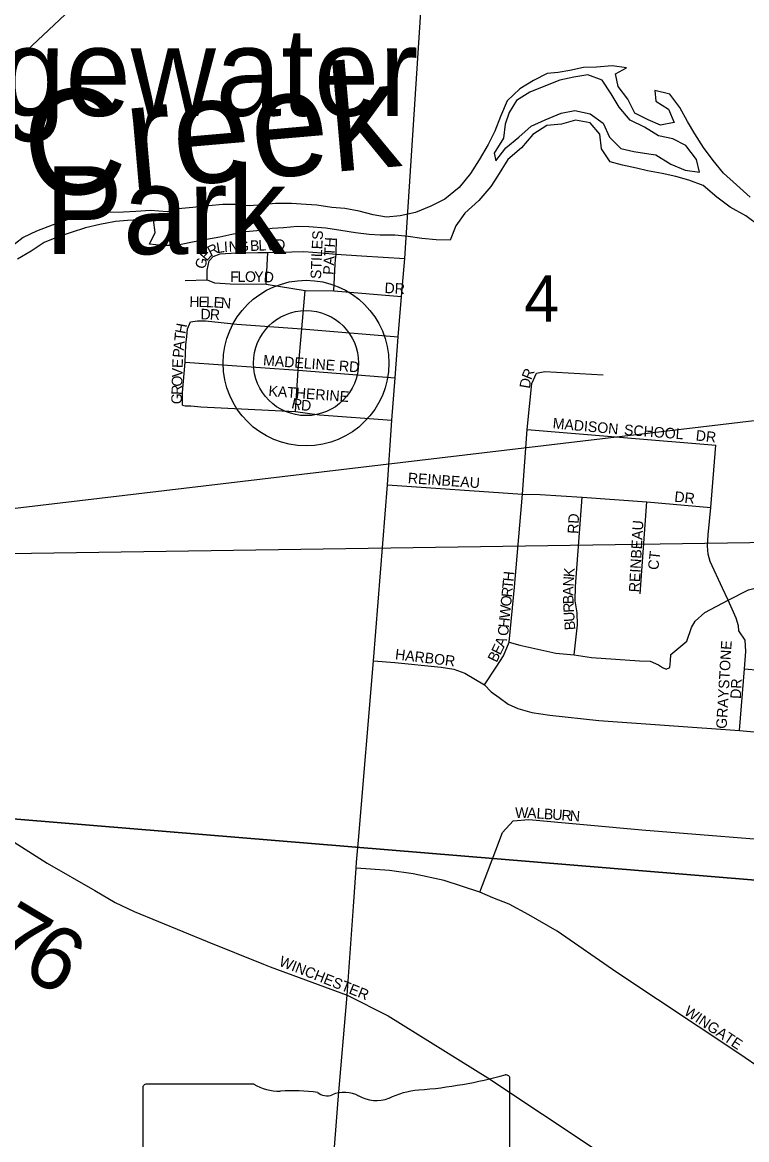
# Model space of a CAD drawing. Extents: x 0 to 34, y 0 to 22.
# Drawn here: x 6.374 to 7.024, y 16.825 to 17.828 of the extents above; entities that cross this region are included whole.
import ezdxf

# ---------------------------------------------------------------- set-up
doc = ezdxf.new("R2010")
doc.units = 0
for name, color, linetype in [('BD_P_Text', 7, 'Continuous'), ('GM_X_City_Street', 7, 'Continuous'), ('GM_X_City_Street_Text', 7, 'Continuous'), ('GM_X_County_Road', 7, 'Continuous'), ('GM_X_County_Road_Text', 7, 'Continuous'), ('GM_X_Interstate_Route', 7, 'Continuous'), ('GM_X_Major_River', 7, 'Continuous'), ('GM_X_Major_River_Text', 7, 'Continuous'), ('GM_X_Section', 7, 'Continuous'), ('GM_X_Section_Text', 7, 'Continuous'), ('GM_X_State_Route', 7, 'Continuous'), ('GM_X_State_Shield', 7, 'Continuous'), ('GM_X_Township_Subdivision', 7, 'Continuous'), ('GM_X_Township_Subdivision_Text', 7, 'Continuous'), ('GM_X_Unincorporated', 7, 'Continuous'), ('GM_X_Unincorporated_Location', 7, 'Continuous'), ('GM_X_Unincorporated_Text', 7, 'Continuous')]:
    doc.layers.add(name, color=color, linetype=linetype)

msp = doc.modelspace()

# ---------------------------------------------------------------- linework, layer by layer
at = {"layer": 'BD_P_Text'}
msp.add_lwpolyline([(9.7485, 17.7931), (5.9787, 17.3454), (9.7485, 17.4014)], close=True, dxfattribs=at)
at = {"layer": 'GM_X_City_Street'}
msp.add_lwpolyline([(6.5904, 16.9823), (6.5965, 16.9798), (6.6655, 16.9545), (6.7025, 16.9357), (6.7917, 16.88), (6.9382, 16.7826), (7.1077, 16.6702), (7.1098, 16.6688)], dxfattribs=at)
at = {"layer": 'GM_X_County_Road'}
msp.add_lwpolyline([(5.1496, 17.8918), (5.1573, 17.8838), (5.1678, 17.876), (5.3625, 17.7509), (5.6653, 17.5523), (5.7694, 17.4837), (5.8147, 17.4543), (5.8758, 17.4145), (5.8966, 17.4004), (5.9787, 17.3454), (5.9879, 17.3394), (6.1472, 17.2345), (6.3013, 17.1331), (6.3963, 17.0731), (6.4389, 17.0483), (6.4571, 17.0376), (6.4744, 17.0295), (6.5397, 17.0026), (6.5904, 16.9823)], dxfattribs=at)
at = {"layer": 'GM_X_Interstate_Route'}
msp.add_lwpolyline([(6.6338, 18.046), (6.5392, 17.957), (6.4517, 17.8729), (6.3828, 17.8077), (6.3064, 17.727), (6.2509, 17.6728), (6.2053, 17.6234), (6.1901, 17.6054)], dxfattribs=at)
at = {"layer": 'GM_X_Major_River'}
for points in [[(7.0273, 17.6715), (7.0152, 17.6825), (7.0034, 17.6931), (6.9943, 17.7045), (6.9856, 17.7159), (6.9777, 17.7284), (6.9712, 17.7394), (6.9644, 17.7519), (6.9553, 17.764), (6.9417, 17.7674), (6.9428, 17.7576), (6.9542, 17.7504), (6.9591, 17.7386), (6.947, 17.736), (6.9357, 17.7409), (6.9239, 17.7469), (6.9175, 17.7595), (6.9088, 17.7708), (6.9065, 17.7822), (6.9164, 17.7875), (6.9035, 17.7894), (6.8895, 17.7883), (6.8777, 17.7879), (6.8656, 17.7852), (6.855, 17.7833), (6.8452, 17.7825), (6.833, 17.7761), (6.8206, 17.7689), (6.8092, 17.7579), (6.8031, 17.7438), (6.7982, 17.7306), (6.7921, 17.7188), (6.7842, 17.7051), (6.7762, 17.6926), (6.766, 17.6801), (6.7531, 17.6695), (6.7406, 17.6634), (6.727, 17.6577), (6.713, 17.6547), (6.7009, 17.6535), (6.6888, 17.6554), (6.6763, 17.6588), (6.6634, 17.6611), (6.6517, 17.6622), (6.6384, 17.6641), (6.6286, 17.6649), (6.6157, 17.6656), (6.6013, 17.6656), (6.5896, 17.6645), (6.5774, 17.6637), (6.5646, 17.6648), (6.554, 17.6648), (6.5411, 17.6637), (6.5271, 17.6621), (6.5138, 17.661), (6.504, 17.6583), (6.4889, 17.6594), (6.4758, 17.6585), (6.4646, 17.6579), (6.4502, 17.6576), (6.4396, 17.656), (6.426, 17.6553), (6.4108, 17.6499), (6.4006, 17.6461), (6.3866, 17.6408), (6.3745, 17.6351), (6.3609, 17.6245)], [(6.9428, 17.7094), (6.9561, 17.7011), (6.969, 17.6958), (6.9818, 17.6939), (6.9792, 17.7053), (6.9697, 17.7178), (6.958, 17.7238), (6.9451, 17.7265), (6.9326, 17.7344), (6.9198, 17.7405), (6.9099, 17.7522), (6.9027, 17.7644), (6.8944, 17.7765), (6.8815, 17.7814), (6.869, 17.7791), (6.8565, 17.7765), (6.8436, 17.7715), (6.8296, 17.7659), (6.8175, 17.7583), (6.8111, 17.7476), (6.8073, 17.737), (6.8058, 17.7245), (6.7974, 17.7108), (6.799, 17.704)], [(7.0364, 17.645), (7.0235, 17.6545), (7.0095, 17.6624), (6.9974, 17.6715), (6.9852, 17.6818), (6.9724, 17.6867), (6.9606, 17.6901), (6.9485, 17.6927), (6.9353, 17.695), (6.9254, 17.6976), (6.9129, 17.7003), (6.9016, 17.7033), (6.894, 17.7147), (6.8925, 17.728), (6.8838, 17.7382), (6.8705, 17.7405), (6.858, 17.737), (6.8448, 17.7359), (6.8323, 17.7276), (6.8221, 17.7158), (6.8099, 17.7052), (6.8005, 17.6904), (6.7944, 17.6809), (6.7838, 17.6684), (6.7713, 17.657), (6.763, 17.6456), (6.7581, 17.6327), (6.7456, 17.6331), (6.7327, 17.6342), (6.7202, 17.6361), (6.7084, 17.6372), (6.6952, 17.6372), (6.6854, 17.638), (6.6729, 17.6395), (6.66, 17.6414), (6.6464, 17.6436), (6.6312, 17.6448), (6.621, 17.6451), (6.6085, 17.644), (6.5983, 17.6432), (6.5843, 17.6413), (6.5744, 17.6402), (6.5619, 17.6379), (6.5513, 17.6356), (6.5392, 17.6333), (6.5252, 17.6307), (6.5123, 17.628), (6.4994, 17.628), (6.4881, 17.6291), (6.493, 17.6398), (6.4915, 17.6511), (6.4786, 17.6511), (6.4684, 17.6504), (6.4574, 17.6496), (6.4434, 17.6469), (6.4305, 17.6439), (6.4177, 17.6397), (6.4044, 17.6352), (6.3934, 17.6306), (6.3817, 17.623), (6.3696, 17.6158)], [(6.799, 17.704), (6.808, 17.7158), (6.8198, 17.7253), (6.8308, 17.7351), (6.8433, 17.7408), (6.8577, 17.7469), (6.8701, 17.7492), (6.8838, 17.7462), (6.8955, 17.7378), (6.9012, 17.7253), (6.9114, 17.7151), (6.9228, 17.7124), (6.9364, 17.7102), (6.9428, 17.7094)]]:
    msp.add_lwpolyline(points, dxfattribs=at)
at = {"layer": 'GM_X_Section'}
for points in [[(6.2087, 18.0808), (6.2447, 18.0791), (6.7511, 18.0375), (7.2561, 17.997), (7.1918, 17.0445), (6.1439, 17.131)], [(6.1439, 17.131), (7.1918, 17.0445), (7.1133, 16.022), (6.0779, 16.1089)]]:
    msp.add_lwpolyline(points, close=True, dxfattribs=at)
at = {"layer": 'GM_X_State_Route'}
for points in [[(6.7306, 17.8193), (6.7383, 17.9387)], [(6.7183, 17.6303), (6.7306, 17.8193)], [(6.6757, 17.0937), (6.6892, 17.2548), (6.7018, 17.413), (6.7056, 17.4709), (6.7086, 17.509), (6.7113, 17.5459), (6.7143, 17.5822), (6.7174, 17.6164), (6.7183, 17.6303)], [(6.674, 17.0738), (6.6757, 17.0937)], [(6.6711, 17.034), (6.6736, 17.0686), (6.674, 17.0738)], [(6.6219, 16.4123), (6.6287, 16.4882), (6.6574, 16.8602), (6.6655, 16.9545), (6.6711, 17.034)]]:
    msp.add_lwpolyline(points, dxfattribs=at)
at = {"layer": 'GM_X_State_Shield'}
for p, q in [((6.8117, 16.7747), (6.8117, 16.8794)), ((6.4821, 16.871), (6.4821, 16.6709)), ((6.5819, 16.8744), (6.4853, 16.8744))]:
    msp.add_line(p, q, dxfattribs=at)
for centre, major_axis, start_param, end_param in [((6.6943, 17.1473), (0.3495, 0), 4.814394, 5.042369), ((6.808, 16.8798), (0.00367, 0), 6.141152, 7.989035), ((6.4859, 16.8714), (0.00382, 0), 1.712693, 3.28349), ((6.6048, 16.8977), (0.037, 0), 4.042523, 4.731795), ((6.6171, 16.7621), (0.133, 0), 1.404758, 1.657858), ((6.6473, 16.8725), (0.0107, 0), 3.836095, 5.185415), ((6.663, 16.8493), (0.0222, 0), 0.950623, 2.079405), ((6.7388, 16.8133), (0.0703, 0), 1.699011, 2.107814), ((6.6917, 16.8811), (0.0267, 0), 4.081561, 5.145723)]:
    msp.add_ellipse(centre, major_axis=major_axis, ratio=0.8, start_param=start_param, end_param=end_param, dxfattribs=at)
at = {"layer": 'GM_X_Township_Subdivision'}
for points in [[(6.6552, 17.6152), (6.6557, 17.6203), (6.656, 17.634)], [(6.5396, 17.597), (6.5398, 17.597), (6.5398, 17.6058), (6.5417, 17.6142), (6.5452, 17.618), (6.5516, 17.6206), (6.5661, 17.6214), (6.5852, 17.6218), (6.5943, 17.6218), (6.6267, 17.6225), (6.6427, 17.6214), (6.6557, 17.6203), (6.6785, 17.6187), (6.7174, 17.6164)], [(6.5928, 17.5932), (6.5943, 17.6218)], [(6.6537, 17.5871), (6.6549, 17.6115), (6.6552, 17.6152)], [(6.52, 17.5966), (6.5396, 17.597)], [(6.5398, 17.597), (6.5463, 17.5943), (6.5516, 17.594), (6.5604, 17.5936), (6.5928, 17.5932), (6.6278, 17.5875), (6.6537, 17.5871), (6.7143, 17.5822)], [(6.6191, 17.4789), (6.6214, 17.5159), (6.6248, 17.5532), (6.6278, 17.5875)], [(6.525, 17.5593), (6.5311, 17.5604), (6.5383, 17.5604), (6.5665, 17.5574), (6.6248, 17.5532), (6.7113, 17.5459)], [(6.5177, 17.4846), (6.5177, 17.496), (6.52, 17.5231), (6.5208, 17.5387), (6.5215, 17.5463), (6.5223, 17.5532), (6.525, 17.5593)], [(6.52, 17.5231), (6.6214, 17.5159), (6.7086, 17.509)], [(6.789, 17.2331), (6.7993, 17.2491), (6.8058, 17.2594), (6.8111, 17.2716), (6.8157, 17.3211), (6.8229, 17.4046), (6.8271, 17.4625), (6.8313, 17.504), (6.8355, 17.5132)], [(6.8355, 17.5132), (6.8431, 17.5147), (6.8953, 17.5117)], [(6.5177, 17.4846), (6.52, 17.4838), (6.5253, 17.4838), (6.5341, 17.4831), (6.6191, 17.4789), (6.6408, 17.4758), (6.7056, 17.4709)], [(6.8271, 17.4625), (6.9967, 17.4485)], [(7.0178, 17.1922), (7.0224, 17.2475), (7.0234, 17.2632), (7.0229, 17.2734), (7.0173, 17.2817), (7.017, 17.2862), (7.0148, 17.2931), (7.0077, 17.3093), (7.0026, 17.3202), (6.9915, 17.3441), (6.9896, 17.3506), (6.989, 17.3579), (6.9896, 17.3679), (6.9921, 17.3927), (6.9967, 17.4485)], [(6.7018, 17.413), (6.8229, 17.4046), (6.8389, 17.4042), (6.8767, 17.4019), (6.9346, 17.3977), (6.9921, 17.3927)], [(6.8694, 17.2602), (6.8725, 17.2872), (6.8721, 17.2979), (6.8702, 17.3086), (6.8706, 17.3215), (6.8767, 17.4019)], [(6.9285, 17.315), (6.9346, 17.3977)], [(6.8111, 17.2716), (6.8206, 17.2689), (6.853, 17.2617), (6.8694, 17.2602), (6.885, 17.2579), (6.9281, 17.2548), (6.9377, 17.2546), (6.9452, 17.2511), (6.9486, 17.2488), (6.952, 17.2472), (6.9554, 17.2487), (6.9559, 17.2547), (6.9563, 17.2604), (6.9704, 17.2724), (6.9746, 17.2846), (6.978, 17.2905), (6.9868, 17.2983), (7.0077, 17.3093), (7.0259, 17.3185), (7.0447, 17.3235), (7.0599, 17.3235), (7.0807, 17.3215)], [(6.6892, 17.2548), (6.7082, 17.2533), (6.7498, 17.2491), (6.7612, 17.2472), (6.7711, 17.2438), (6.789, 17.2331), (6.7947, 17.227), (6.8019, 17.2217), (6.8101, 17.2159), (6.8188, 17.212), (6.8313, 17.2085), (6.8476, 17.206), (6.8915, 17.2013), (7.0178, 17.1922), (7.0411, 17.1902)], [(7.0224, 17.2475), (7.0761, 17.2429), (7.139, 17.2369)], [(6.7846, 17.0468), (6.799, 17.0847), (6.8049, 17.1005), (6.8145, 17.1111), (6.8287, 17.1121), (6.9301, 17.103), (7.0796, 17.0909), (7.1907, 17.0817)], [(7.1734, 16.8369), (7.1425, 16.8409), (7.1212, 16.846), (7.0943, 16.8561), (7.0731, 16.8653), (7.0391, 16.8871), (7.0173, 16.9018), (6.9078, 16.9748), (6.8541, 17.0118), (6.8287, 17.0265), (6.811, 17.0361), (6.7963, 17.0417), (6.7846, 17.0468), (6.7527, 17.0574), (6.7248, 17.0635), (6.7035, 17.0665), (6.6736, 17.0686)]]:
    msp.add_lwpolyline(points, dxfattribs=at)
at = {"layer": 'GM_X_Unincorporated'}
for radius in [0.0744, 0.0472]:
    msp.add_circle((6.6286, 17.5223), radius, dxfattribs=at)
at = {"layer": 'GM_X_Unincorporated_Location'}
msp.add_line((6.6286, 17.5223), (6.6286, 17.5223), dxfattribs=at)

# ---------------------------------------------------------------- texts
at = {"layer": 'GM_X_City_Street_Text'}
msp.add_text('WINCHESTER', height=0.00947, rotation=338.3155, dxfattribs=at).set_placement((6.6036, 16.9811))
at = {"layer": 'GM_X_County_Road_Text'}
for s, rotation, p in [('7', 329.1352, (6.34, 16.9924)), ('6', 330.5361, (6.3713, 16.9737))]:
    msp.add_text(s, height=0.0568, rotation=rotation, dxfattribs=at).set_placement(p)
at = {"layer": 'GM_X_Major_River_Text'}
msp.add_text('Creek', height=0.09469, rotation=5.0012, dxfattribs=at).set_placement((6.3788, 17.67))
at = {"layer": 'GM_X_Section_Text'}
msp.add_text('4', height=0.0419, rotation=0, dxfattribs=at).set_placement((6.8246, 17.5594))
at = {"layer": 'GM_X_Township_Subdivision_Text'}
for s, rotation, p in [('STILES', 87.5141, (6.642, 17.5977)), ('L', 9.2198, (6.5489, 17.621)), ('I', 3.7181, (6.5552, 17.622)), ('N', 2.164, (6.5593, 17.6223)), ('G', 2.1421, (6.5677, 17.6226)), ('B', 2.1615, (6.5785, 17.623)), ('L', 2.1585, (6.586, 17.6233)), ('V', 2.1575, (6.5926, 17.6236)), ('D', 2.1421, (6.601, 17.6239)), ('PATH', 86.8249, (6.6533, 17.6014)), ('E', 48.6727, (6.5393, 17.6133)), ('R', 27.521, (6.543, 17.6178)), ('G', 76.1864, (6.5379, 17.6063)), ('F', 359.7541, (6.5605, 17.5953)), ('L', 359.7268, (6.5671, 17.5953)), ('O', 359.7337, (6.5738, 17.5953)), ('Y', 359.7453, (6.5821, 17.5953)), ('D', 355.9315, (6.5903, 17.5952)), ('DR', 356.9776, (6.6989, 17.5853)), ('H', 359.2349, (6.5238, 17.5728)), ('E', 359.2435, (6.5321, 17.5727)), ('L', 357.7039, (6.5387, 17.5726)), ('E', 355.8988, (6.5453, 17.5724)), ('N', 355.9067, (6.5519, 17.5719)), ('D', 358.2948, (6.5337, 17.5617)), ('R', 356.5979, (6.542, 17.5615)), ('T', 84.3645, (6.5196, 17.5417)), ('H', 79.2044, (6.5202, 17.5481)), ('A', 84.3525, (6.5188, 17.5334)), ('P', 85.132, (6.5182, 17.5268)), ('MADELINE RD', 355.7863, (6.5898, 17.5203)), ('E', 87.5947, (6.5178, 17.5177)), ('O', 88.7204, (6.5174, 17.5011)), ('V', 88.7104, (6.5176, 17.5094)), ('R', 67.8603, (6.8307, 17.5067)), ('R', 88.6887, (6.5172, 17.4936)), ('KATHERINE', 355.6549, (6.5946, 17.4928)), ('D', 80.5161, (6.8295, 17.499)), ('G', 88.7104, (6.517, 17.4853)), ('R', 346.4939, (6.6149, 17.482)), ('D', 356.3388, (6.6239, 17.4799)), ('MADISON', 354.7255, (6.8498, 17.4637)), ('SCHOOL', 355.6669, (6.9139, 17.4578)), ('DR', 353.9832, (6.9782, 17.4528)), ('REINBEAU', 355.9135, (6.7198, 17.4145)), ('DR', 353.9946, (6.959, 17.3978)), ('RD', 86.9775, (6.8729, 17.3687)), ('REINBEAU', 86.7282, (6.9279, 17.3162)), ('CT', 83.6638, (6.9449, 17.3361)), ('H', 84.4395, (6.8148, 17.3257)), ('N', 86.6104, (6.8688, 17.3214)), ('K', 85.8209, (6.8693, 17.3297)), ('R', 84.4339, (6.8134, 17.3116)), ('T', 84.4283, (6.8141, 17.3191)), ('A', 89.5409, (6.8687, 17.3132)), ('O', 84.4177, (6.8126, 17.3033)), ('B', 91.6518, (6.8689, 17.3058)), ('W', 84.4266, (6.8115, 17.2925)), ('R', 93.5323, (6.8694, 17.2984)), ('H', 84.417, (6.8107, 17.2842)), ('U', 93.5218, (6.8699, 17.2901)), ('B', 93.5233, (6.8704, 17.2826)), ('C', 84.4104, (6.81, 17.2768)), ('E', 63.7282, (6.803, 17.2594)), ('A', 69.0935, (6.8064, 17.2663)), ('GRAYSTONE', 86.5923, (7.0062, 17.1935)), ('HARBOR', 353.1208, (6.7082, 17.2562)), ('B', 63.7065, (6.7997, 17.2527)), ('DR', 86.989, (7.019, 17.2204)), ('W', 359.6974, (6.8163, 17.1137)), ('A', 357.0699, (6.827, 17.1136)), ('L', 355.8171, (6.8353, 17.1132)), ('B', 355.7466, (6.8419, 17.1127)), ('U', 355.7815, (6.8494, 17.1122)), ('R', 355.7708, (6.8577, 17.1116)), ('N', 355.7555, (6.8652, 17.111)), ('WINGATE', 326.3109, (6.9673, 16.9376))]:
    msp.add_text(s, height=0.00947, rotation=rotation, dxfattribs=at).set_placement(p)
at = {"layer": 'GM_X_Unincorporated_Text'}
for s, p in [('Edgewater', (6.2246, 17.7444)), ('Park', (6.3938, 17.6202))]:
    msp.add_text(s, height=0.07898, rotation=0, dxfattribs=at).set_placement(p)

doc.saveas('drawing.dxf')
